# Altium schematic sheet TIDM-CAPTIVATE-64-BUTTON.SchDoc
size 431 x 279 mm; Date: Not shown in title block; ApprovedBy: Not shown in title block; CheckedBy: Not shown in title block; Author: Not shown in title block; CompanyName: Not shown in title block; Engineer: Not shown in title block; Organization: Not shown in title block; Address1: Not shown in title block; Address2: Not shown in title block; Address3: Not shown in title block; Address4: Not shown in title block; DocumentNumber: 1; Revision: Use project parameter SCH_Rev; SheetNumber: 2; SheetTotal: 3; PageSetup: Record=PageOptions¦CenterHorizontal=True¦CenterVertical=True¦PrintScale=0.62¦XCorrection=1.00¦YCorrection=1.00¦PrintKind=0¦BorderSize=5000000¦LeftOffset=0¦BottomOffset=0¦Orientation=2¦PaperLength=1000¦PaperWidth=1000¦Scale=100¦PaperSource=15¦PrintQuality=-3¦MediaType=1¦DitherType=10¦PrintScaleMode=1¦PaperKind=Letter¦PaperIndex=1
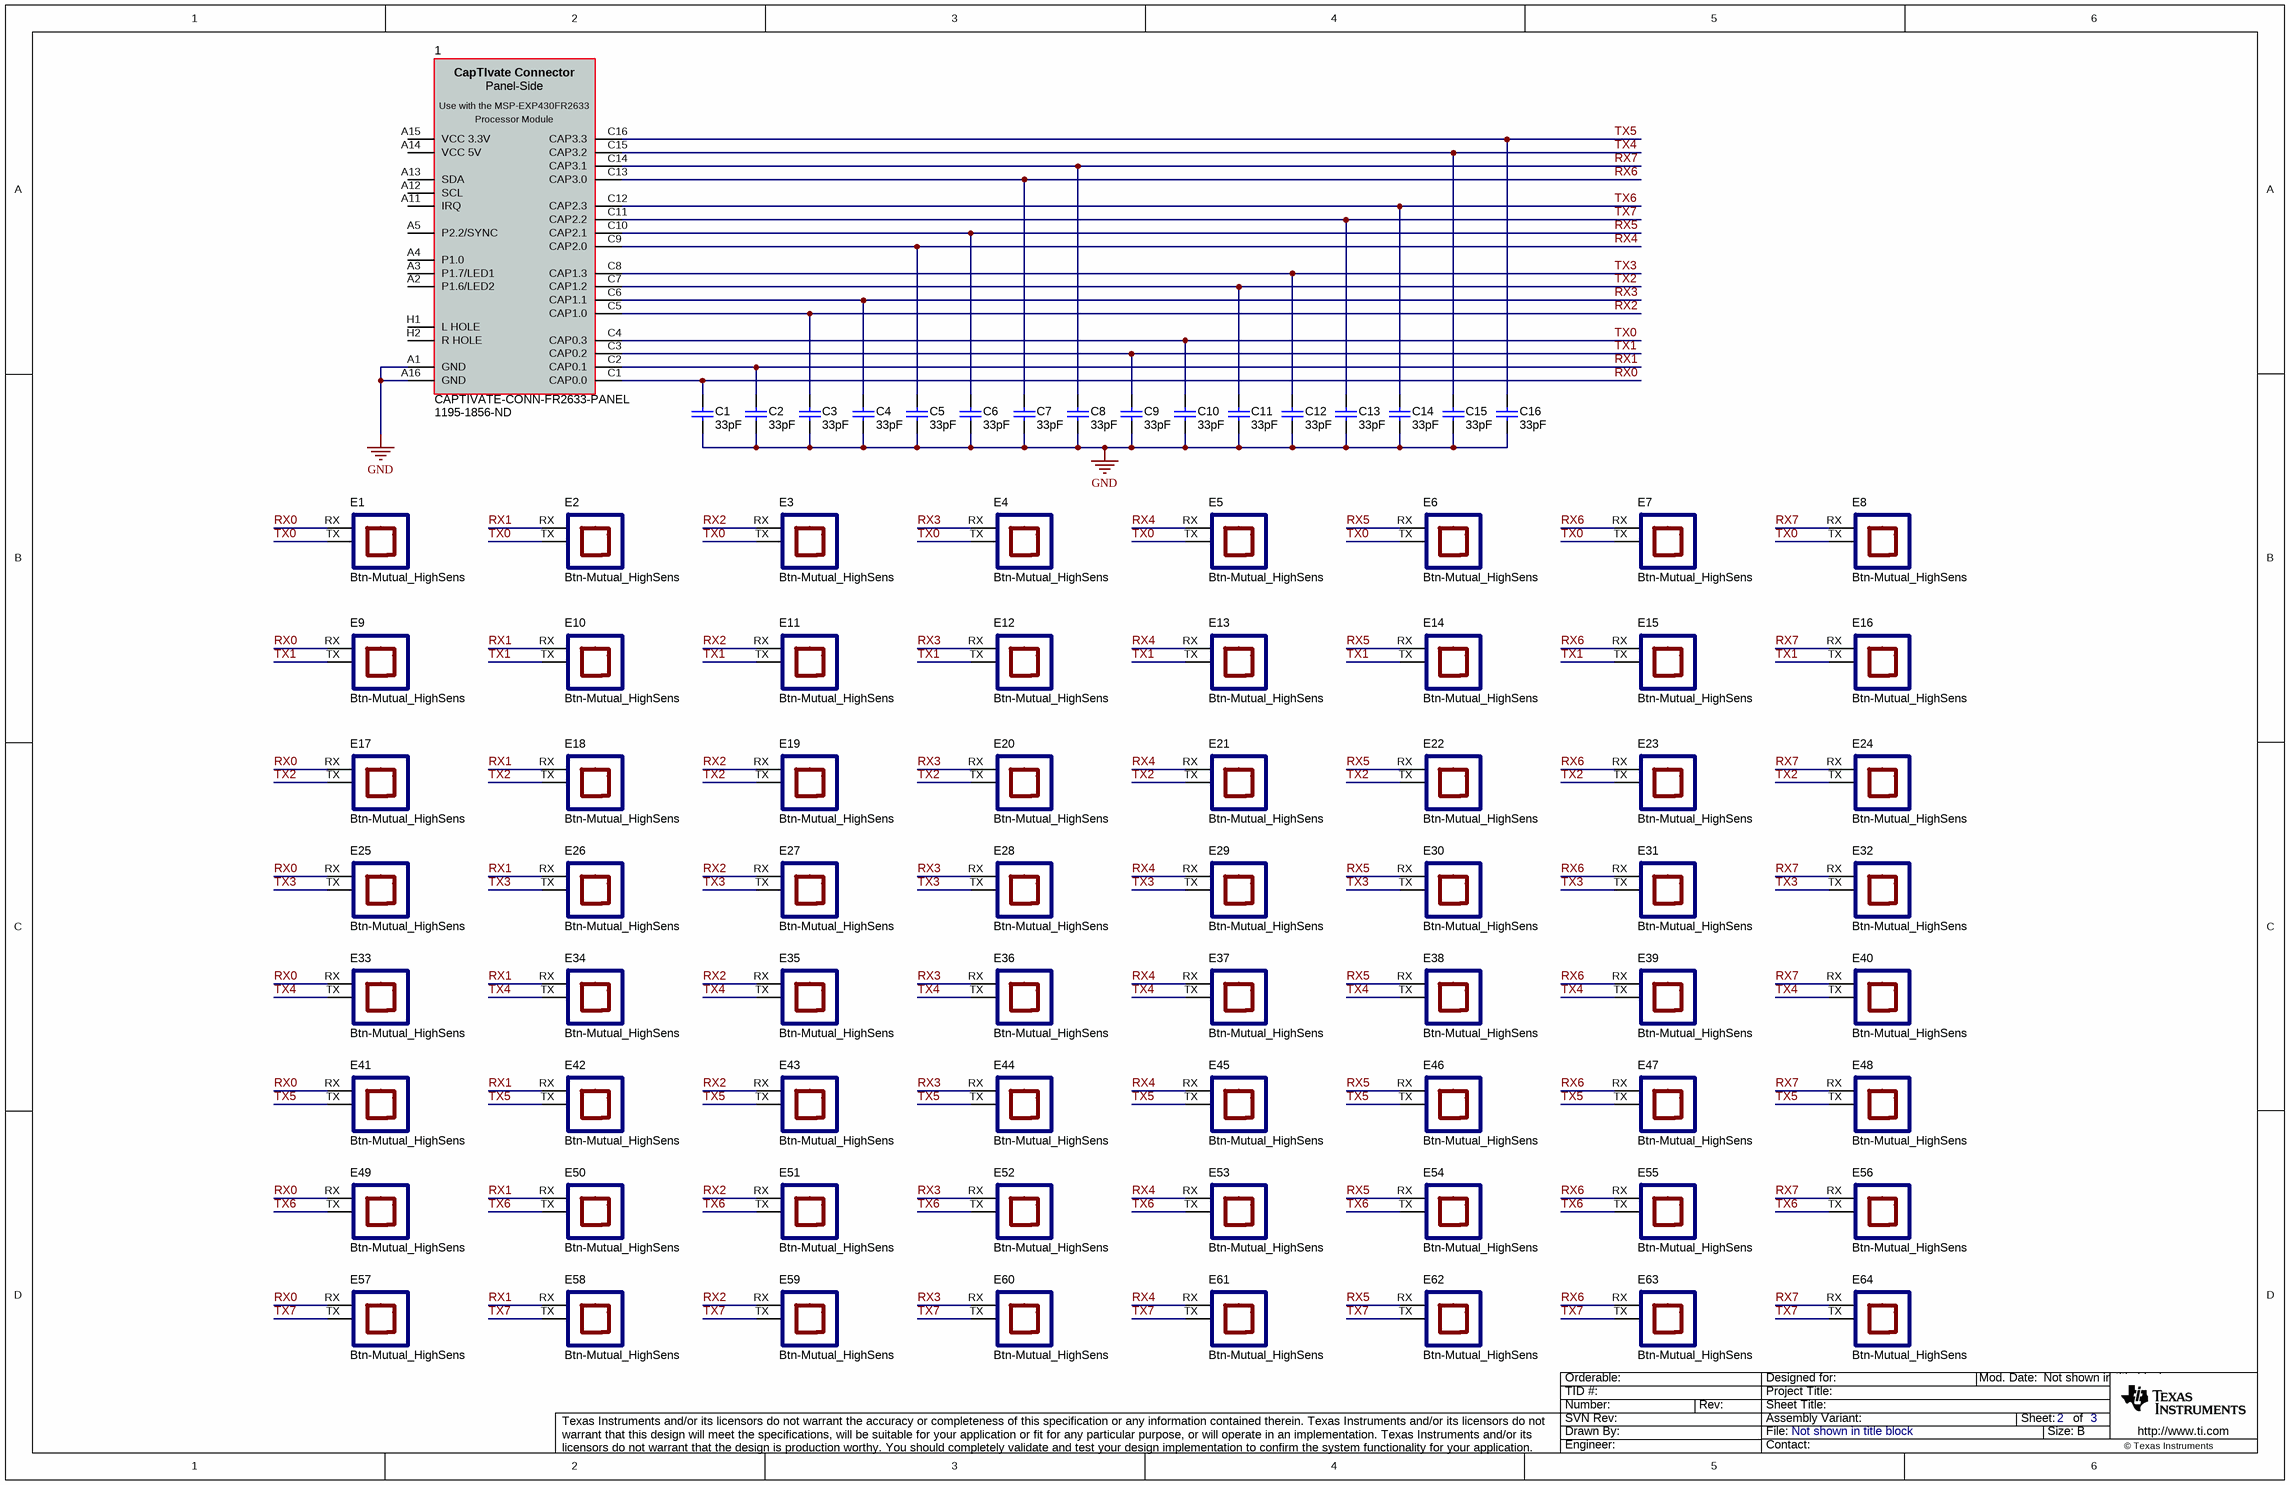
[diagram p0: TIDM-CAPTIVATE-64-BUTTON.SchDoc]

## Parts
1  CAPTIVATE-CONN-FR2633-PANEL  Supplier Part Number 1: 1195-1856-ND  [CAPTIVATE-CONN-48]
C1  ValueDisplayed: 33pF  [0603]  (hidden comment: 06035A330JAT2A)
C2  ValueDisplayed: 33pF  [0603]  (hidden comment: 06035A330JAT2A)
C3  ValueDisplayed: 33pF  [0603]  (hidden comment: 06035A330JAT2A)
C4  ValueDisplayed: 33pF  [0603]  (hidden comment: 06035A330JAT2A)
C5  ValueDisplayed: 33pF  [0603]  (hidden comment: 06035A330JAT2A)
C6  ValueDisplayed: 33pF  [0603]  (hidden comment: 06035A330JAT2A)
C7  ValueDisplayed: 33pF  [0603]  (hidden comment: 06035A330JAT2A)
C8  ValueDisplayed: 33pF  [0603]  (hidden comment: 06035A330JAT2A)
C9  ValueDisplayed: 33pF  [0603]  (hidden comment: 06035A330JAT2A)
C10  ValueDisplayed: 33pF  [0603]  (hidden comment: 06035A330JAT2A)
C11  ValueDisplayed: 33pF  [0603]  (hidden comment: 06035A330JAT2A)
C12  ValueDisplayed: 33pF  [0603]  (hidden comment: 06035A330JAT2A)
C13  ValueDisplayed: 33pF  [0603]  (hidden comment: 06035A330JAT2A)
C14  ValueDisplayed: 33pF  [0603]  (hidden comment: 06035A330JAT2A)
C15  ValueDisplayed: 33pF  [0603]  (hidden comment: 06035A330JAT2A)
C16  ValueDisplayed: 33pF  [0603]  (hidden comment: 06035A330JAT2A)
E1  Btn-Mutual_HighSens  [electrode-mutual-highsensitivity-cut-rotated]  (no BOM)
E2  Btn-Mutual_HighSens  [electrode-mutual-highsensitivity-cut-rotated]  (no BOM)
E3  Btn-Mutual_HighSens  [electrode-mutual-highsensitivity-cut-rotated]  (no BOM)
E4  Btn-Mutual_HighSens  [electrode-mutual-highsensitivity-cut-rotated]  (no BOM)
E5  Btn-Mutual_HighSens  [electrode-mutual-highsensitivity-cut-rotated]  (no BOM)
E6  Btn-Mutual_HighSens  [electrode-mutual-highsensitivity-cut-rotated]  (no BOM)
E7  Btn-Mutual_HighSens  [electrode-mutual-highsensitivity-cut-rotated]  (no BOM)
E8  Btn-Mutual_HighSens  [electrode-mutual-highsensitivity-cut-rotated]  (no BOM)
E9  Btn-Mutual_HighSens  [electrode-mutual-highsensitivity-cut-rotated]  (no BOM)
E10  Btn-Mutual_HighSens  [electrode-mutual-highsensitivity-cut-rotated]  (no BOM)
E11  Btn-Mutual_HighSens  [electrode-mutual-highsensitivity-cut-rotated]  (no BOM)
E12  Btn-Mutual_HighSens  [electrode-mutual-highsensitivity-cut-rotated]  (no BOM)
E13  Btn-Mutual_HighSens  [electrode-mutual-highsensitivity-cut-rotated]  (no BOM)
E14  Btn-Mutual_HighSens  [electrode-mutual-highsensitivity-cut-rotated]  (no BOM)
E15  Btn-Mutual_HighSens  [electrode-mutual-highsensitivity-cut-rotated]  (no BOM)
E16  Btn-Mutual_HighSens  [electrode-mutual-highsensitivity-cut-rotated]  (no BOM)
E17  Btn-Mutual_HighSens  [electrode-mutual-highsensitivity-cut-rotated]  (no BOM)
E18  Btn-Mutual_HighSens  [electrode-mutual-highsensitivity-cut-rotated]  (no BOM)
E19  Btn-Mutual_HighSens  [electrode-mutual-highsensitivity-cut-rotated]  (no BOM)
E20  Btn-Mutual_HighSens  [electrode-mutual-highsensitivity-cut-rotated]  (no BOM)
E21  Btn-Mutual_HighSens  [electrode-mutual-highsensitivity-cut-rotated]  (no BOM)
E22  Btn-Mutual_HighSens  [electrode-mutual-highsensitivity-cut-rotated]  (no BOM)
E23  Btn-Mutual_HighSens  [electrode-mutual-highsensitivity-cut-rotated]  (no BOM)
E24  Btn-Mutual_HighSens  [electrode-mutual-highsensitivity-cut-rotated]  (no BOM)
E25  Btn-Mutual_HighSens  [electrode-mutual-highsensitivity-cut-rotated]  (no BOM)
E26  Btn-Mutual_HighSens  [electrode-mutual-highsensitivity-cut-rotated]  (no BOM)
E27  Btn-Mutual_HighSens  [electrode-mutual-highsensitivity-cut-rotated]  (no BOM)
E28  Btn-Mutual_HighSens  [electrode-mutual-highsensitivity-cut-rotated]  (no BOM)
E29  Btn-Mutual_HighSens  [electrode-mutual-highsensitivity-cut-rotated]  (no BOM)
E30  Btn-Mutual_HighSens  [electrode-mutual-highsensitivity-cut-rotated]  (no BOM)
E31  Btn-Mutual_HighSens  [electrode-mutual-highsensitivity-cut-rotated]  (no BOM)
E32  Btn-Mutual_HighSens  [electrode-mutual-highsensitivity-cut-rotated]  (no BOM)
E33  Btn-Mutual_HighSens  [electrode-mutual-highsensitivity-cut-rotated]  (no BOM)
E34  Btn-Mutual_HighSens  [electrode-mutual-highsensitivity-cut-rotated]  (no BOM)
E35  Btn-Mutual_HighSens  [electrode-mutual-highsensitivity-cut-rotated]  (no BOM)
E36  Btn-Mutual_HighSens  [electrode-mutual-highsensitivity-cut-rotated]  (no BOM)
E37  Btn-Mutual_HighSens  [electrode-mutual-highsensitivity-cut-rotated]  (no BOM)
E38  Btn-Mutual_HighSens  [electrode-mutual-highsensitivity-cut-rotated]  (no BOM)
E39  Btn-Mutual_HighSens  [electrode-mutual-highsensitivity-cut-rotated]  (no BOM)
E40  Btn-Mutual_HighSens  [electrode-mutual-highsensitivity-cut-rotated]  (no BOM)
E41  Btn-Mutual_HighSens  [electrode-mutual-highsensitivity-cut-rotated]  (no BOM)
E42  Btn-Mutual_HighSens  [electrode-mutual-highsensitivity-cut-rotated]  (no BOM)
E43  Btn-Mutual_HighSens  [electrode-mutual-highsensitivity-cut-rotated]  (no BOM)
E44  Btn-Mutual_HighSens  [electrode-mutual-highsensitivity-cut-rotated]  (no BOM)
E45  Btn-Mutual_HighSens  [electrode-mutual-highsensitivity-cut-rotated]  (no BOM)
E46  Btn-Mutual_HighSens  [electrode-mutual-highsensitivity-cut-rotated]  (no BOM)
E47  Btn-Mutual_HighSens  [electrode-mutual-highsensitivity-cut-rotated]  (no BOM)
E48  Btn-Mutual_HighSens  [electrode-mutual-highsensitivity-cut-rotated]  (no BOM)
E49  Btn-Mutual_HighSens  [electrode-mutual-highsensitivity-cut-rotated]  (no BOM)
E50  Btn-Mutual_HighSens  [electrode-mutual-highsensitivity-cut-rotated]  (no BOM)
E51  Btn-Mutual_HighSens  [electrode-mutual-highsensitivity-cut-rotated]  (no BOM)
E52  Btn-Mutual_HighSens  [electrode-mutual-highsensitivity-cut-rotated]  (no BOM)
E53  Btn-Mutual_HighSens  [electrode-mutual-highsensitivity-cut-rotated]  (no BOM)
E54  Btn-Mutual_HighSens  [electrode-mutual-highsensitivity-cut-rotated]  (no BOM)
E55  Btn-Mutual_HighSens  [electrode-mutual-highsensitivity-cut-rotated]  (no BOM)
E56  Btn-Mutual_HighSens  [electrode-mutual-highsensitivity-cut-rotated]  (no BOM)
E57  Btn-Mutual_HighSens  [electrode-mutual-highsensitivity-cut-rotated]  (no BOM)
E58  Btn-Mutual_HighSens  [electrode-mutual-highsensitivity-cut-rotated]  (no BOM)
E59  Btn-Mutual_HighSens  [electrode-mutual-highsensitivity-cut-rotated]  (no BOM)
E60  Btn-Mutual_HighSens  [electrode-mutual-highsensitivity-cut-rotated]  (no BOM)
E61  Btn-Mutual_HighSens  [electrode-mutual-highsensitivity-cut-rotated]  (no BOM)
E62  Btn-Mutual_HighSens  [electrode-mutual-highsensitivity-cut-rotated]  (no BOM)
E63  Btn-Mutual_HighSens  [electrode-mutual-highsensitivity-cut-rotated]  (no BOM)
E64  Btn-Mutual_HighSens  [electrode-mutual-highsensitivity-cut-rotated]  (no BOM)

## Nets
GND: 1.A1(GND) 1.A16(GND) C1.2 C2.2 C3.2 C4.2 C5.2 C6.2 C7.2 C8.2 C9.2 C10.2 C11.2 C12.2 C13.2 C14.2 C15.2 C16.2
RX0: 1.C1(CAP0.0) C1.1 E1.RX E9.RX E17.RX E25.RX E33.RX E41.RX E49.RX E57.RX
RX1: 1.C2(CAP0.1) C2.1 E2.RX E10.RX E18.RX E26.RX E34.RX E42.RX E50.RX E58.RX
RX2: 1.C5(CAP1.0) C3.1 E3.RX E11.RX E19.RX E27.RX E35.RX E43.RX E51.RX E59.RX
RX3: 1.C6(CAP1.1) C4.1 E4.RX E12.RX E20.RX E28.RX E36.RX E44.RX E52.RX E60.RX
RX4: 1.C9(CAP2.0) C5.1 E5.RX E13.RX E21.RX E29.RX E37.RX E45.RX E53.RX E61.RX
RX5: 1.C10(CAP2.1) C6.1 E6.RX E14.RX E22.RX E30.RX E38.RX E46.RX E54.RX E62.RX
RX6: 1.C13(CAP3.0) C7.1 E7.RX E15.RX E23.RX E31.RX E39.RX E47.RX E55.RX E63.RX
RX7: 1.C14(CAP3.1) C8.1 E8.RX E16.RX E24.RX E32.RX E40.RX E48.RX E56.RX E64.RX
TX0: 1.C4(CAP0.3) C10.1 E1.TX E2.TX E3.TX E4.TX E5.TX E6.TX E7.TX E8.TX
TX1: 1.C3(CAP0.2) C9.1 E9.TX E10.TX E11.TX E12.TX E13.TX E14.TX E15.TX E16.TX
TX2: 1.C7(CAP1.2) C11.1 E17.TX E18.TX E19.TX E20.TX E21.TX E22.TX E23.TX E24.TX
TX3: 1.C8(CAP1.3) C12.1 E25.TX E26.TX E27.TX E28.TX E29.TX E30.TX E31.TX E32.TX
TX4: 1.C15(CAP3.2) C15.1 E33.TX E34.TX E35.TX E36.TX E37.TX E38.TX E39.TX E40.TX
TX5: 1.C16(CAP3.3) C16.1 E41.TX E42.TX E43.TX E44.TX E45.TX E46.TX E47.TX E48.TX
TX6: 1.C12(CAP2.3) C14.1 E49.TX E50.TX E51.TX E52.TX E53.TX E54.TX E55.TX E56.TX
TX7: 1.C11(CAP2.2) C13.1 E57.TX E58.TX E59.TX E60.TX E61.TX E62.TX E63.TX E64.TX

Not connected (* = marked no-connect by the designer): 1 A2(P1.6/LED2) A3(P1.7/LED1) A4(P1.0) A5(P2.2/SYNC) A11(IRQ) A12(SCL) A13(SDA) A14(VCC_5V) A15(VCC_3.3V) H1(L_HOLE) H2(R_HOLE)

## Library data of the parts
1 = CAPTIVATE-CONN-MSP-EXP430FR2633-PANEL: CapTIvate Panel-Side Connector, 3x16, 100mil, TH, RA, M, MSP-EXP430FR2633; Manufacturer: Used in BOM report; SymbolCreator: a0273983; U/M: EA, IN, or GM
C1-C16 = 06035A330JAT2A: CAP, CERM, 33 pF, 50 V, +/- 5%, C0G/NP0, 0603; Manufacturer: AVX; Polarized: N; CompType: Capacitor; Value: 33pF; U/M: EA; Cap_F: 0.000000000033; Tolerance_%: 5; ESR_ohm: 0.209; Value1: 0.209 ohm; VDC_V: 50; Value2: 50V; TaMin_C: -55; TaMax_C: 125
E1-E64 = btn-mutual-highsens: Capacitive Button, Mutual, 2-layer, 10mm, High Sensitivity; Manufacturer: None; SymbolCreator: a0273983; CompType: Electrode; U/M: EA, IN, or GM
